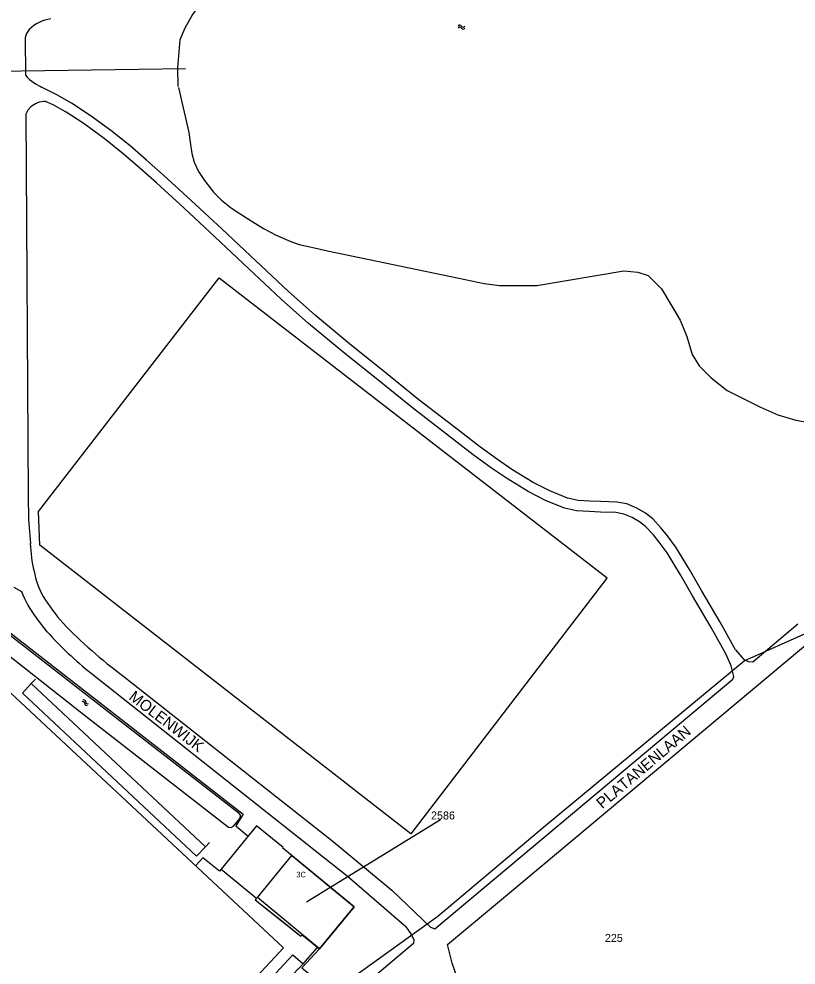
# Model space of a CAD drawing. Extents: x 148816 to 151297, y 399515 to 402500.
# Drawn here: x 149526 to 149700.3, y 400552.9 to 400765.2 of the extents above; entities that cross this region are included whole.
import ezdxf

# ---------------------------------------------------------------- set-up
doc = ezdxf.new("R2010")
doc.units = 0
for name, color, linetype in [('B01 Hoofdgebouw  [D] Norm', 7, 'Continuous'), ('B01 Hoofdgebouw  [T] Norm', 7, 'Continuous'), ('B01 hoofgebouw', 7, 'Continuous'), ('G01 perceelsgrens', 7, 'Continuous'), ('G02 sectiegrens', 7, 'Continuous'), ('S05 Water  Norm', 7, 'Continuous'), ('T04 Haag heg  [D] Gem', 7, 'Continuous'), ('T09 Insteek water  [T] Norm', 7, 'Continuous'), ('V00 Kant verharding algemeen  [T] Norm', 7, 'Continuous'), ('W10 Duiker  [T] Gem', 7, 'Continuous'), ('Z01 perceelnummer', 7, 'Continuous'), ('Z02 Huisnummer  [Tekst] Norm', 7, 'Continuous'), ('Z06 straatnaam', 7, 'Continuous')]:
    doc.layers.add(name, color=color, linetype=linetype)

msp = doc.modelspace()

# ---------------------------------------------------------------- linework, layer by layer
at = {"layer": 'B01 Hoofdgebouw  [D] Norm'}
for p, q in [((149528.79, 400616.09), (149526.8, 400613.97)), ((149529.71, 400617.06), (149528.79, 400616.09)), ((149567.85, 400579.46), (149528.79, 400616.09)), ((149526.8, 400613.97), (149565.87, 400577.34)), ((149565.87, 400577.34), (149567.85, 400579.46)), ((149568.77, 400580.43), (149567.85, 400579.46))]:
    msp.add_line(p, q, dxfattribs=at)
at = {"layer": 'B01 Hoofdgebouw  [T] Norm'}
for p, q in [((149579.32, 400584.18), (149571.36, 400574.46)), ((149585.29, 400579.28), (149579.32, 400584.18)), ((149585.19, 400579.16), (149585.29, 400579.28)), ((149601.23, 400566.03), (149585.19, 400579.16)), ((149571.36, 400574.46), (149579.3, 400567.96)), ((149579.3, 400567.96), (149579, 400567.6)), ((149579, 400567.6), (149589.23, 400559.41)), ((149593.41, 400556.55), (149601.23, 400566.03)), ((149589.23, 400559.41), (149589.52, 400559.76)), ((149589.52, 400559.76), (149593.41, 400556.55))]:
    msp.add_line(p, q, dxfattribs=at)
at = {"layer": 'B01 hoofgebouw'}
for points in [[(149585.19, 400579.16), (149585.29, 400579.28), (149579.32, 400584.18), (149571.36, 400574.46), (149579.3, 400567.96), (149579, 400567.6), (149585.37, 400562.59)], [(149585.37, 400562.59), (149589.23, 400559.41), (149589.52, 400559.76), (149593.41, 400556.55), (149601.23, 400566.03), (149585.19, 400579.16)]]:
    msp.add_lwpolyline(points, dxfattribs=at)
at = {"layer": 'G01 perceelsgrens'}
msp.add_lwpolyline([(149601.23, 400566.03), (149593.41, 400556.55), (149579.54, 400568.12), (149587.22, 400577.5), (149601.23, 400566.03)], dxfattribs=at)
at = {"layer": 'G02 sectiegrens'}
msp.add_lwpolyline([(149540.2, 400500), (149564.79, 400520.43), (149598.68, 400548.56), (149619.97, 400563.9), (149644.11, 400584.23), (149688.7, 400621.22), (149778.93, 400661.52)], dxfattribs=at)
at = {"layer": 'S05 Water  Norm'}
for centre, start, end in [((149624.89, 400762.92), 27.4391, 151.2942), ((149624.9, 400763.37), 27.4391, 151.2942), ((149625.65, 400763.31), 207.4391, 331.2942), ((149625.65, 400763.76), 207.4391, 331.2942), ((149540.35, 400611.62), 357.745, 121.6), ((149540.57, 400612.01), 357.745, 121.6), ((149541.2, 400611.59), 177.745, 301.6), ((149541.42, 400611.97), 177.745, 301.6)]:
    msp.add_arc(centre, 0.425, start, end, dxfattribs=at)
at = {"layer": 'T04 Haag heg  [D] Gem'}
for p, q in [((149530.43, 400654.71), (149570.94, 400707.13)), ((149570.94, 400707.13), (149657.93, 400639.78)), ((149530.72, 400647.1), (149530.43, 400654.71)), ((149613.94, 400582.37), (149530.72, 400647.1)), ((149657.9, 400639.76), (149613.94, 400582.37)), ((149574.66, 400584.2), (149577.43, 400581.87))]:
    msp.add_line(p, q, dxfattribs=at)
for points in [[(149500.04, 400638.49), (149509, 400639.11), (149576.33, 400586.78), (149574.66, 400584.2)], [(149589.78, 400553.24), (149592.89, 400556.82)], [(149536.21, 400500), (149587.44, 400555.21), (149589.78, 400553.24), (149588.67, 400552.01), (149588.41, 400551.91), (149574.73, 400536.63), (149556.68, 400516.55), (149553.16, 400512.93), (149542.48, 400502.73)]]:
    msp.add_lwpolyline(points, dxfattribs=at)
at = {"layer": 'T09 Insteek water  [T] Norm'}
for points in [[(149648.6, 400796.55), (149648.02, 400796.28), (149637.01, 400792.94), (149628.16, 400790.57), (149610.51, 400786.26), (149594.46, 400781.2), (149583.83, 400777.23), (149574.68, 400773.86), (149571.47, 400772.32), (149567.75, 400770.09), (149564.92, 400766.16), (149563.21, 400763.13), (149562.11, 400760.46), (149561.56, 400754.22), (149561.67, 400750.03)], [(149561.8, 400749.78), (149564.15, 400739.66), (149564.46, 400737.53), (149564.79, 400734.97), (149565.35, 400733.07), (149566.31, 400730.95), (149567.61, 400728.94), (149569.67, 400726.32), (149571.44, 400724.54), (149573.7, 400722.74), (149577.31, 400720.37), (149580.89, 400718.13), (149583.7, 400716.64), (149586.97, 400715.26), (149588.88, 400714.6), (149592.29, 400713.85), (149595.19, 400713.17), (149624.65, 400706.99), (149630.35, 400705.84), (149633.81, 400705.35), (149642.21, 400705.37), (149661.68, 400708.65), (149664.8, 400708.38), (149667.15, 400707.59), (149670.13, 400704.63), (149674.35, 400697.63), (149675.82, 400693.92), (149676.98, 400689.89), (149678.59, 400687.35), (149681.26, 400684.67), (149684.85, 400681.84), (149692.16, 400678.17), (149696.22, 400676.34), (149700.24, 400675.2), (149708.28, 400673.77)], [(149505.46, 400637.47), (149521.52, 400624.1), (149541.05, 400608.8), (149573.02, 400583.9), (149573.6, 400583.81), (149574.13, 400584.09), (149575.61, 400585.93), (149575.75, 400586.55), (149575.39, 400586.95), (149547.4, 400608.72), (149525.49, 400625.75), (149509.44, 400638.32), (149508.93, 400638.62), (149508.35, 400638.69), (149505.51, 400638.41), (149505.18, 400637.92), (149505.46, 400637.47)]]:
    msp.add_lwpolyline(points, dxfattribs=at)
at = {"layer": 'V00 Kant verharding algemeen  [T] Norm'}
for p, q in [((149527.4, 400760.94), (149527.49, 400752.57)), ((149527.49, 400752.57), (149527.86, 400752.07)), ((149527.86, 400752.07), (149528.36, 400751.57)), ((149528.36, 400751.57), (149529.75, 400750.6)), ((149529.75, 400750.6), (149530.84, 400750)), ((149530.84, 400750), (149531.11, 400749.87)), ((149528.63, 400745.36), (149528.04, 400744.67)), ((149528.04, 400744.67), (149527.54, 400743.83)), ((149527.54, 400743.83), (149528.06, 400658.28)), ((149528.06, 400658.28), (149528.19, 400652.9)), ((149528.19, 400652.9), (149528.58, 400647.47)), ((149524.91, 400637.74), (149526.59, 400636.75)), ((149532.34, 400627.71), (149529.87, 400630.87)), ((149690.62, 400620.98), (149700.72, 400629.46)), ((149635.61, 400568.79), (149705.47, 400627.31)), ((149685.77, 400620.08), (149684.58, 400622.73)), ((149686.73, 400623.68), (149688.54, 400621.59)), ((149686.39, 400617.65), (149685.77, 400620.08)), ((149688.54, 400621.59), (149689.61, 400621.01)), ((149689.61, 400621.01), (149690.62, 400620.98)), ((149542.21, 400618.39), (149599.61, 400572.94)), ((149549.27, 400617.91), (149596.14, 400580.95)), ((149686.17, 400617.05), (149686.39, 400617.65)), ((149619.32, 400561.07), (149686.17, 400617.05)), ((149596.14, 400580.95), (149609.65, 400569.75)), ((149599.61, 400572.94), (149606.24, 400567.28)), ((149609.65, 400569.75), (149618.31, 400561.48)), ((149622.15, 400557.53), (149635.61, 400568.79)), ((149606.24, 400567.28), (149612.79, 400561.59)), ((149618.31, 400561.48), (149619.32, 400561.07)), ((149614.62, 400558.68), (149614.53, 400557.8)), ((149614.53, 400557.8), (149599.95, 400545.55)), ((149623.19, 400553.34), (149622.15, 400557.53)), ((149624.28, 400550.15), (149623.19, 400553.34))]:
    msp.add_line(p, q, dxfattribs=at)
for points in [[(149686.73, 400623.68), (149683.33, 400629.85), (149679.14, 400636.97), (149676.44, 400641.65), (149673.36, 400646.7), (149671.49, 400649.25), (149670.09, 400650.96), (149668.18, 400653.02), (149666.55, 400654.34), (149664.61, 400655.45), (149662.39, 400656.37), (149660.11, 400656.81), (149656.53, 400656.9), (149654.07, 400656.99), (149651.43, 400657.18), (149649.09, 400657.7), (149645.08, 400659.29), (149641.37, 400661.21), (149636.6, 400664.1), (149633.34, 400666.31), (149629.32, 400669.26), (149623.37, 400673.87), (149615.73, 400679.76), (149607.26, 400686.62), (149600.58, 400691.94), (149592.5, 400698.63), (149586.44, 400704.07), (149579.12, 400710.92), (149571.59, 400717.99), (149564.65, 400724.41), (149558.46, 400730.12), (149554.64, 400733.48), (149550.93, 400736.69), (149546.6, 400740.18), (149541.97, 400743.54), (149537.82, 400746.28), (149534.53, 400748.17), (149531.11, 400749.87)], [(149684.58, 400622.73), (149681.29, 400628.69), (149677.12, 400635.79), (149674.42, 400640.46), (149671.42, 400645.4), (149669.64, 400647.81), (149668.32, 400649.42), (149666.58, 400651.3), (149665.22, 400652.4), (149663.58, 400653.35), (149661.72, 400654.11), (149659.86, 400654.47), (149656.46, 400654.56), (149653.94, 400654.66), (149651.09, 400654.85), (149648.39, 400655.45), (149644.11, 400657.16), (149640.22, 400659.17), (149635.34, 400662.13), (149631.99, 400664.4), (149627.91, 400667.4), (149621.94, 400672.02), (149614.28, 400677.92), (149605.79, 400684.8), (149599.1, 400690.12), (149590.97, 400696.86), (149584.86, 400702.34), (149577.52, 400709.21), (149569.99, 400716.28), (149563.06, 400722.69), (149556.9, 400728.38), (149553.1, 400731.71), (149549.43, 400734.89), (149545.17, 400738.32), (149540.64, 400741.61), (149536.6, 400744.28), (149533.73, 400745.92), (149531.98, 400746.68)], [(149534.45, 400502.05), (149585.36, 400556.83), (149502.54, 400634.12), (149451.56, 400579.29), (149480.3, 400552.55)], [(149571.36, 400574.46), (149570.98, 400574), (149567.26, 400577.03), (149565.73, 400575.26)], [(149593.41, 400556.55), (149589.48, 400552.34), (149591.8, 400550.43), (149585.43, 400542.72), (149591.28, 400537.89)]]:
    msp.add_lwpolyline(points, dxfattribs=at)
for centre, radius, start, end in [((149534.15, 400757.13), 8.1, 97.0517, 135.8881), ((149530.95, 400760.27), 3.61, 136.2526, 169.3717), ((149531.96, 400741.83), 4.85, 89.708, 133.3038), ((149558.52, 400648.37), 29.96, 181.7189, 193.6288), ((149546.28, 400644.14), 17.11, 189.5345, 209.9637), ((149548.58, 400645.16), 23.55, 200.9344, 217.3732), ((149569.57, 400659.42), 44.94, 211.9998, 221.4935), ((149608.84, 400699.23), 100.8, 223.6578, 233.7763), ((149597.71, 400687.06), 88.29, 222.2328, 231.0506), ((149603.63, 400553.8), 12.02, 23.9456, 40.3832), ((149418.38, 401033.28), 566.92, 299.144, 302.8106)]:
    msp.add_arc(centre, radius, start, end, dxfattribs=at)
at = {"layer": 'W10 Duiker  [T] Gem'}
msp.add_line((149516.72, 400753.43), (149563.36, 400754.03), dxfattribs=at)
at = {"layer": 'Z01 perceelnummer'}
msp.add_lwpolyline([(149620.58, 400585.5), (149590.55, 400567.03)], dxfattribs=at)

# ---------------------------------------------------------------- texts
for s, p in [('2586', (149618.45, 400585.6)), ('225', (149657.44, 400558.13))]:
    msp.add_text(s, height=1.8, dxfattribs=at).set_placement(p)
at = {"layer": 'Z02 Huisnummer  [Tekst] Norm'}
msp.add_text('3C', height=1.25, dxfattribs=at).set_placement((149588.24, 400572.62))
at = {"layer": 'Z06 straatnaam'}
for s, rotation, p in [('MOLENWIJK', 322.4768, (149550.49, 400612.69)), ('PLATANENLAAN', 40.334, (149656.85, 400587.89))]:
    msp.add_text(s, height=2.5, rotation=rotation, dxfattribs=at).set_placement(p)

doc.saveas('drawing.dxf')
